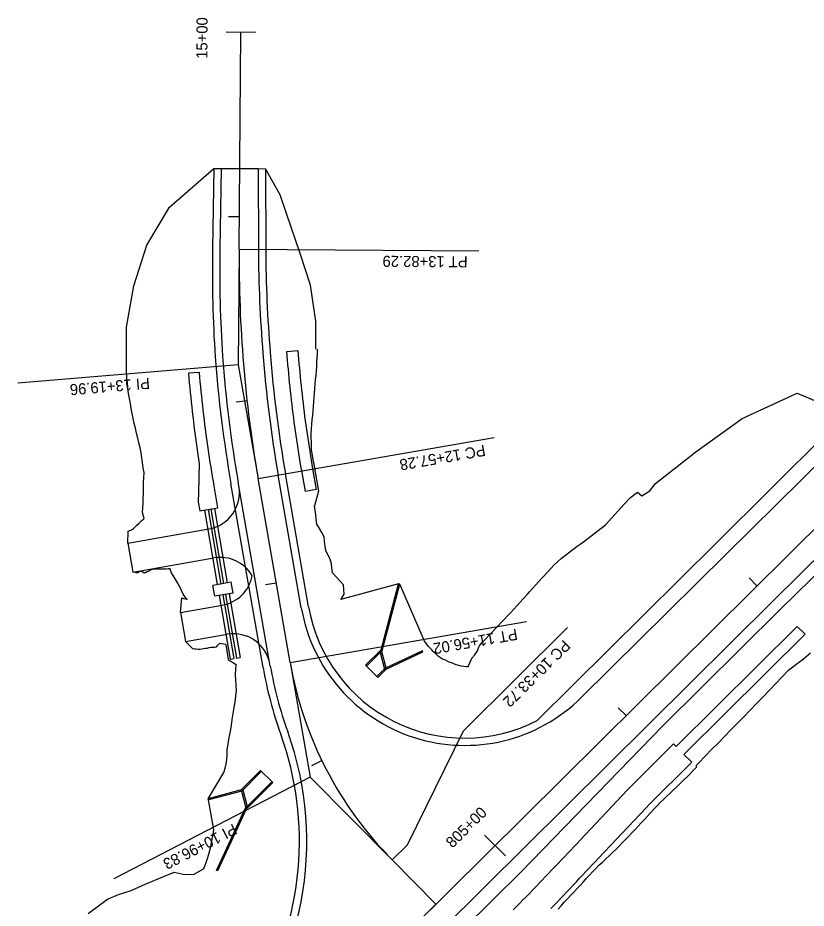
# Model space of a CAD drawing. Extents: x 1237212 to 1293764, y 379349 to 410301.
# Drawn here: x 1283553.8 to 1283981.4, y 404564.5 to 405047.3 of the extents above; entities that cross this region are included whole.
import ezdxf

# ---------------------------------------------------------------- set-up
doc = ezdxf.new("R2010")
doc.units = 0
for name, color, linetype in [('B-Sub-Footing', 7, 'Continuous'), ('B-Sub-Pier Cap', 7, 'Continuous'), ('B-Tbl-Title Block', 7, 'Continuous'), ('B-Title Block (No Plot)', 7, 'Continuous'), ('R_Axis', 7, 'Continuous'), ('R_Axis Annot', 7, 'Continuous'), ('R_Exist Surface', 7, 'Continuous'), ('R_Grid Annot', 7, 'Continuous'), ('R_Shld', 7, 'Continuous')]:
    doc.layers.add(name, color=color, linetype=linetype)

msp = doc.modelspace()

# ---------------------------------------------------------------- linework, layer by layer
for points in [[(1283666.7, 405039.61), (1283682.69, 405039.49)], [(1283666.7, 405039.61), (1283682.69, 405039.49)], [(1283667.97, 404939.6), (1283673.97, 404939.55)], [(1283672.14, 404839.05), (1283678.11, 404839.71)], [(1283688.08, 404739.97), (1283693.99, 404741)], [(1283713.3, 404641.92), (1283718.69, 404644.53)], [(1283774.89, 404561.11), (1283786.25, 404572.37)]]:
    msp.add_lwpolyline(points)
at = {"layer": 'B-Sub-Footing'}
for p, q in [((1283613.47, 404762.48), (1283657.44, 404770.15)), ((1283613.47, 404762.48), (1283616.22, 404746.72)), ((1283616.22, 404746.72), (1283660.19, 404754.39)), ((1283641.96, 404724.82), (1283664.66, 404728.78)), ((1283641.96, 404724.82), (1283644.71, 404709.06)), ((1283644.71, 404709.06), (1283667.41, 404713.02))]:
    msp.add_line(p, q, dxfattribs=at)
for centre, start, end in [((1283654, 404789.86), 279.8958, 9.8958), ((1283663.63, 404734.69), 30.3831, 99.8958), ((1283661.22, 404748.48), 279.8958, 349.4085), ((1283670.85, 404693.31), 9.8958, 99.8958)]:
    msp.add_arc(centre, 20, start, end, dxfattribs=at)
at = {"layer": 'B-Sub-Pier Cap'}
for p, q in [((1283699.71, 404866.4), (1283705.7, 404866.86)), ((1283652.29, 404855.06), (1283646.31, 404854.53)), ((1283715.65, 404791.45), (1283709.74, 404790.42)), ((1283652.5, 404779.91), (1283662.36, 404781.61)), ((1283669.47, 404741.23), (1283659.61, 404739.53)), ((1283660.65, 404733.62), (1283659.61, 404739.53)), ((1283670.51, 404735.32), (1283669.47, 404741.23)), ((1283670.51, 404735.32), (1283660.65, 404733.62)), ((1283976.49, 404717.27), (1283910.8, 404652.15)), ((1283980.72, 404713.01), (1283976.49, 404717.27)), ((1283915.03, 404647.89), (1283980.72, 404713.01)), ((1283910.8, 404652.15), (1283909.39, 404653.57)), ((1283919.25, 404643.63), (1283915.03, 404647.89))]:
    msp.add_line(p, q, dxfattribs=at)
for points in [[(1283709.74, 404790.42), (1283707.76, 404801.77), (1283707.35, 404804.14), (1283706.95, 404806.52), (1283706.55, 404808.9), (1283706.17, 404811.29), (1283705.79, 404813.67), (1283705.43, 404816.06), (1283705.07, 404818.44), (1283704.72, 404820.83), (1283704.38, 404823.22), (1283704.05, 404825.61), (1283703.72, 404828), (1283703.41, 404830.4), (1283703.1, 404832.79), (1283702.8, 404835.18), (1283702.51, 404837.58), (1283702.23, 404839.98), (1283701.96, 404842.38), (1283701.7, 404844.78), (1283701.44, 404847.18), (1283701.19, 404849.58), (1283700.96, 404851.98), (1283700.73, 404854.38), (1283700.51, 404856.78), (1283700.3, 404859.19), (1283700.09, 404861.59), (1283699.9, 404864), (1283699.71, 404866.4)], [(1283705.7, 404866.86), (1283705.88, 404864.47), (1283706.07, 404862.09), (1283706.27, 404859.7), (1283706.48, 404857.32), (1283706.7, 404854.94), (1283706.93, 404852.56), (1283707.16, 404850.18), (1283707.41, 404847.8), (1283707.66, 404845.42), (1283707.92, 404843.04), (1283708.19, 404840.67), (1283708.47, 404838.29), (1283708.76, 404835.91), (1283709.05, 404833.54), (1283709.36, 404831.17), (1283709.67, 404828.8), (1283709.99, 404826.43), (1283710.32, 404824.06), (1283710.66, 404821.69), (1283711, 404819.32), (1283711.36, 404816.96), (1283711.72, 404814.59), (1283712.09, 404812.23), (1283712.47, 404809.87), (1283712.86, 404807.51), (1283713.26, 404805.15), (1283713.67, 404802.79), (1283715.65, 404791.45)], [(1283646.31, 404854.53), (1283646.54, 404851.94), (1283646.78, 404849.34), (1283647.02, 404846.74), (1283647.28, 404844.15), (1283647.55, 404841.55), (1283647.82, 404838.96), (1283648.11, 404836.36), (1283648.4, 404833.77), (1283648.71, 404831.18), (1283649.02, 404828.59), (1283649.34, 404826), (1283649.67, 404823.41), (1283650.01, 404820.83), (1283650.36, 404818.24), (1283650.72, 404815.66), (1283651.09, 404813.08), (1283651.47, 404810.5), (1283651.86, 404807.92), (1283652.21, 404805.62), (1283652.13, 404803.25), (1283652.05, 404800.59), (1283651.98, 404797.93), (1283651.92, 404795.27), (1283651.87, 404792.62), (1283651.81, 404790.07), (1283651.67, 404784.68), (1283652.5, 404779.91)], [(1283662.36, 404781.61), (1283660.29, 404793.49), (1283659.85, 404796.05), (1283659.42, 404798.6), (1283659, 404801.15), (1283658.58, 404803.7), (1283658.18, 404806.26), (1283657.79, 404808.82), (1283657.4, 404811.38), (1283657.03, 404813.94), (1283656.66, 404816.5), (1283656.31, 404819.06), (1283655.96, 404821.62), (1283655.62, 404824.19), (1283655.29, 404826.75), (1283654.97, 404829.32), (1283654.66, 404831.89), (1283654.36, 404834.46), (1283654.07, 404837.03), (1283653.79, 404839.6), (1283653.52, 404842.17), (1283653.25, 404844.75), (1283653, 404847.32), (1283652.75, 404849.9), (1283652.52, 404852.47), (1283652.29, 404855.06)], [(1283909.39, 404653.57), (1283886.18, 404630.56), (1283884.48, 404628.61), (1283858.78, 404601.42), (1283857.06, 404599.6), (1283855.34, 404597.78), (1283853.63, 404595.96), (1283851.91, 404594.14), (1283850.19, 404592.31), (1283849.69, 404591.78), (1283848.49, 404590.52), (1283846.76, 404588.71), (1283845.04, 404586.89), (1283843.31, 404585.08), (1283841.59, 404583.27), (1283839.87, 404581.45), (1283838.14, 404579.64), (1283836.42, 404577.82), (1283834.74, 404576.05), (1283833.01, 404574.31), (1283831.25, 404572.53), (1283829.5, 404570.75), (1283827.74, 404568.97), (1283825.98, 404567.19), (1283824.22, 404565.41), (1283822.47, 404563.63)], [(1283842.91, 404564.4), (1283844.68, 404566.19), (1283846.41, 404568.01), (1283848.13, 404569.82), (1283849.85, 404571.64), (1283851.57, 404573.45), (1283853.29, 404575.26), (1283855.02, 404577.08), (1283856.74, 404578.89), (1283858.47, 404580.7), (1283859.68, 404581.98), (1283860.19, 404582.52), (1283861.91, 404584.34), (1283863.62, 404586.16), (1283865.34, 404587.98), (1283867.06, 404589.8), (1283868.77, 404591.61), (1283894.56, 404618.9), (1283896.19, 404620.77), (1283919.25, 404643.63)]]:
    msp.add_lwpolyline(points, dxfattribs=at)
at = {"layer": 'B-Tbl-Title Block'}
for p, q in [((1283664.16, 404965.64), (1283663.4, 404921.92)), ((1283664.16, 404965.64), (1283684.16, 404965.5)), ((1283684.16, 404965.5), (1283684.27, 404921.77)), ((1283937.75, 404756.35), (1284008.92, 404826.6)), ((1283707.55, 404727.3), (1283694.99, 404799.32)), ((1283963.1, 404730.79), (1284034.21, 404801.09)), ((1283690.72, 404695.78), (1283673.31, 404795.54)), ((1283859.57, 404678.85), (1283937.75, 404756.35)), ((1283732.12, 404501.81), (1283963.1, 404730.79))]:
    msp.add_line(p, q, dxfattribs=at)
for centre, radius, start, end in [((1284368.45, 404909.96), 705.15, 179.02775, 183.75514), ((1284368.04, 404923.6), 683.77, 180.15305, 184.88011), ((1284368.31, 404916.78), 683.49, 184.30872, 189.89583), ((1284368.31, 404916.78), 705.49, 184.30872, 189.89583), ((1283796.21, 404742.77), 90, 189.8958, 314.75), ((1283899.6, 404732.22), 212.04, 189.8958, 199.8404), ((1283535.54, 404600.86), 175, 318.458, 19.8404)]:
    msp.add_arc(centre, radius, start, end, dxfattribs=at)
at = {"layer": 'B-Title Block (No Plot)'}
for p, q in [((1283673.84, 404921.85), (1283674.7, 405039.55)), ((1283673.84, 404921.85), (1283674.7, 405039.55)), ((1283673.84, 404921.85), (1283674.7, 405039.55)), ((1283673.84, 404921.85), (1283674.7, 405039.55)), ((1283723.67, 404510.34), (1284167.7, 404950.51)), ((1283723.67, 404510.34), (1284167.7, 404950.51)), ((1283725.52, 404512.17), (1284086.2, 404869.72)), ((1283701.55, 404697.67), (1283684.15, 404797.43)), ((1283701.55, 404697.67), (1283684.15, 404797.43)), ((1283701.55, 404697.67), (1283684.15, 404797.43)), ((1283780.57, 404566.74), (1283756.83, 404590.69)), ((1283780.57, 404566.74), (1283756.83, 404590.69)), ((1283780.57, 404566.74), (1283756.83, 404590.69))]:
    msp.add_line(p, q, dxfattribs=at)
for centre, radius, start, end in [((1284368.31, 404916.78), 694.49, 179.58194, 189.89583), ((1284368.31, 404916.78), 694.49, 179.58194, 189.89583), ((1284368.31, 404916.78), 694.49, 179.58194, 189.89583), ((1284368.31, 404916.78), 694.49, 179.58194, 189.89583), ((1283899.6, 404732.22), 201.04, 189.8958, 224.75), ((1283899.6, 404732.22), 201.04, 189.8958, 224.75), ((1283899.6, 404732.22), 201.04, 189.8958, 224.75), ((1283899.6, 404732.22), 201.04, 189.8958, 224.75)]:
    msp.add_arc(centre, radius, start, end, dxfattribs=at)
at = {"layer": 'R_Axis'}
msp.add_line((1283765.12, 404598.91), (1283795.45, 404660.71), dxfattribs=at)
for points in [[(1283673.84, 404921.85), (1283673.38, 404859.17), (1283684.15, 404797.43)], [(1283673.84, 404921.85), (1283803.83, 404920.9)], [(1283673.38, 404859.17), (1283553.79, 404849.26)], [(1283684.15, 404797.43), (1283812.22, 404819.77)], [(1283701.55, 404697.67), (1283829.62, 404720.01)], [(1283795.45, 404660.71), (1283851.99, 404716.75)], [(1283701.55, 404697.67), (1283712.4, 404635.51), (1283756.83, 404590.69)], [(1283712.4, 404635.51), (1283605.79, 404580.43)], [(1283756.83, 404590.69), (1283765.12, 404598.91)]]:
    msp.add_lwpolyline(points, dxfattribs=at)
at = {"layer": 'R_Axis Annot'}
for p, q in [((1283655.02, 404780.35), (1283656.99, 404780.69)), ((1283655.02, 404780.35), (1283661.98, 404739.94)), ((1283656.99, 404780.69), (1283663.95, 404740.28)), ((1283658.47, 404780.94), (1283660.44, 404781.28)), ((1283658.47, 404780.94), (1283665.43, 404740.54)), ((1283660.44, 404781.28), (1283667.4, 404740.88)), ((1283663.95, 404740.28), (1283661.98, 404739.94)), ((1283667.4, 404740.88), (1283665.43, 404740.54)), ((1283750.77, 404704.6), (1283760.32, 404740.34)), ((1283751.36, 404704.25), (1283760.97, 404740.17)), ((1283760.32, 404740.34), (1283760.97, 404740.17)), ((1283668.42, 404734.96), (1283666.45, 404734.62)), ((1283666.45, 404734.62), (1283672.4, 404700.13)), ((1283668.42, 404734.96), (1283674.37, 404700.47)), ((1283664.97, 404734.37), (1283663, 404734.03)), ((1283663, 404734.03), (1283668.95, 404699.54)), ((1283664.97, 404734.37), (1283670.92, 404699.88)), ((1283742.42, 404696.24), (1283750.77, 404704.6)), ((1283742.89, 404695.77), (1283751.36, 404704.25)), ((1283750.06, 404703.89), (1283752.85, 404693.48)), ((1283750.77, 404704.6), (1283753.56, 404694.19)), ((1283773.21, 404704.1), (1283753.17, 404694.74)), ((1283753.56, 404694.19), (1283773.5, 404703.5)), ((1283773.5, 404703.5), (1283773.21, 404704.1)), ((1283668.95, 404699.54), (1283670.92, 404699.88)), ((1283672.4, 404700.13), (1283674.37, 404700.47)), ((1283742.42, 404696.24), (1283749.02, 404689.64)), ((1283748.55, 404690.12), (1283753.22, 404694.78)), ((1283749.02, 404689.64), (1283753.56, 404694.19)), ((1283674.89, 404628.64), (1283685.48, 404639.24)), ((1283675.24, 404628.04), (1283685.95, 404638.76)), ((1283685.48, 404639.24), (1283692.08, 404632.64)), ((1283674.89, 404628.64), (1283657.03, 404623.84)), ((1283674.89, 404628.64), (1283677.69, 404618.23)), ((1283675.6, 404629.35), (1283678.4, 404618.94)), ((1283677.09, 404618.58), (1283691.61, 404633.11)), ((1283677.69, 404618.23), (1283692.08, 404632.64)), ((1283657.03, 404623.84), (1283657.2, 404623.2)), ((1283675.24, 404628.04), (1283657.2, 404623.2)), ((1283661.47, 404584.97), (1283677.13, 404618.62)), ((1283677.69, 404618.23), (1283662.07, 404584.69)), ((1283662.07, 404584.69), (1283661.47, 404584.97))]:
    msp.add_line(p, q, dxfattribs=at)
at = {"layer": 'R_Exist Surface'}
for p, q in [((1283666.56, 404707.53), (1283667.96, 404699.37)), ((1283667.96, 404699.37), (1283672.21, 404696.6))]:
    msp.add_line(p, q, dxfattribs=at)
for points in [[(1283612.81, 404859.86), (1283612.81, 404879.61), (1283616.64, 404901.93), (1283623.83, 404924.02), (1283636.07, 404944.66), (1283660.16, 404965.67)], [(1283715.43, 404867.59), (1283715.43, 404882.73), (1283712.6, 404902.41), (1283706.84, 404919.46), (1283699.53, 404941.1), (1283696.06, 404951.39), (1283688.15, 404965.47)], [(1283713.1, 404812.26), (1283713.04, 404814.8), (1283712.98, 404817.2), (1283712.93, 404819.61), (1283712.94, 404822.02), (1283713.07, 404824.44), (1283713.28, 404826.88), (1283713.51, 404829.31), (1283713.73, 404831.74), (1283713.96, 404834.16), (1283714.19, 404836.58), (1283714.39, 404838.99), (1283714.52, 404841.39), (1283714.65, 404843.79), (1283714.87, 404846.2), (1283715.09, 404848.6), (1283715.31, 404851), (1283715.53, 404853.39), (1283715.75, 404855.79), (1283715.9, 404858.17), (1283716.04, 404860.55), (1283716.2, 404862.92), (1283716.31, 404865.3), (1283716.35, 404867.66)], [(1283622.39, 404775.74), (1283621.44, 404779.1), (1283621.56, 404781.66), (1283621.7, 404784.22), (1283621.83, 404786.8), (1283621.9, 404789.58), (1283621.91, 404792.35), (1283621.98, 404795.12), (1283622.09, 404797.89), (1283622.23, 404800.66), (1283621.81, 404803.35), (1283621.42, 404806.04), (1283621.03, 404808.73), (1283620.64, 404811.42), (1283620.14, 404814.09), (1283619.47, 404816.75), (1283618.81, 404819.4), (1283618.18, 404822.07), (1283617.56, 404824.73), (1283616.96, 404827.4), (1283616.38, 404830.08), (1283615.82, 404832.76), (1283615.28, 404835.44), (1283614.89, 404838.14), (1283614.41, 404840.83), (1283613.89, 404843.52), (1283613.38, 404846.22), (1283612.9, 404848.91), (1283612.81, 404859.86)], [(1283899.59, 404794.85), (1283921.44, 404811.94), (1283946.62, 404830.09), (1283976.38, 404843.72), (1284003.02, 404832.56)], [(1283713.1, 404812.26), (1283713.46, 404810.03), (1283713.85, 404807.67), (1283714.25, 404805.32), (1283714.65, 404802.96), (1283716.8, 404790.64), (1283714.75, 404782.69)], [(1283798.05, 404695.39), (1283798.92, 404697.54), (1283799.95, 404700.05), (1283801.65, 404701.89), (1283803.01, 404704.07), (1283803.98, 404706.65), (1283805.67, 404708.49), (1283807.36, 404710.34), (1283809.05, 404712.18), (1283810.8, 404713.97), (1283812.57, 404715.73), (1283814.29, 404717.55), (1283816.01, 404719.37), (1283817.72, 404721.19), (1283819.44, 404723.01), (1283821.16, 404724.83), (1283822.84, 404726.68), (1283824.51, 404728.54), (1283826.19, 404730.4), (1283827.88, 404732.25), (1283828.39, 404732.82), (1283830.14, 404734.74), (1283831.24, 404735.96), (1283834.61, 404739.66), (1283837.98, 404743.37), (1283841.35, 404747.07), (1283844.72, 404750.77), (1283848.43, 404754.13), (1283852.47, 404757.16), (1283856.5, 404760.19), (1283860.54, 404763.22), (1283864.58, 404766.25), (1283868.61, 404769.28), (1283872.57, 404772.4), (1283875.93, 404776.11), (1283879.29, 404779.82), (1283882.65, 404783.53), (1283886.01, 404787.24), (1283889.85, 404790.13), (1283892.16, 404788.14), (1283896.61, 404790.75), (1283899.59, 404794.85)], [(1283715.97, 404772.75), (1283715.66, 404775.23), (1283715.35, 404777.72), (1283715.02, 404780.2), (1283714.75, 404782.69)], [(1283613.47, 404762.48), (1283613.57, 404768.89), (1283614.55, 404769.27), (1283615.53, 404769.65), (1283616.49, 404770.35), (1283617.45, 404771.25), (1283618.4, 404772.16), (1283619.35, 404773.06), (1283620.31, 404773.97), (1283621.26, 404774.87), (1283622.22, 404775.69), (1283622.39, 404775.74)], [(1283798.05, 404695.39), (1283797.06, 404695.41), (1283795.66, 404695.55), (1283794.28, 404695.78), (1283792.92, 404696.1), (1283791.6, 404696.5), (1283790.3, 404696.98), (1283789.04, 404697.52), (1283787.79, 404697.99), (1283786.57, 404698.52), (1283785.39, 404699.11), (1283784.19, 404699.57), (1283783.07, 404700.23), (1283782.02, 404701.06), (1283781.02, 404701.92), (1283780.05, 404702.79), (1283779.13, 404703.68), (1283778.24, 404704.58), (1283777.38, 404705.5), (1283776.56, 404706.42), (1283775.78, 404707.36), (1283775.04, 404708.31), (1283774.33, 404709.26), (1283760.97, 404740.17), (1283760.32, 404740.34), (1283729.06, 404731.89), (1283730.87, 404734.75), (1283730.48, 404739.75), (1283728.46, 404741.94), (1283726.47, 404744.13), (1283724.51, 404746.32), (1283724.12, 404748.8), (1283723.97, 404751.31), (1283723.15, 404753.7), (1283721.97, 404756.03), (1283720.81, 404758.37), (1283720.44, 404760.84), (1283720.19, 404763.34), (1283719.86, 404765.82), (1283718.65, 404768.14), (1283717.35, 404770.45), (1283715.97, 404772.75)], [(1283616.87, 404746.83), (1283617.92, 404746.6), (1283618.96, 404746.44), (1283619.89, 404746.98), (1283620.81, 404747.52)], [(1283620.81, 404747.52), (1283621.97, 404746.56), (1283622.98, 404746.56), (1283623.93, 404747), (1283624.87, 404747.44), (1283625.82, 404747.89), (1283626.76, 404748.33), (1283627.74, 404748.52)], [(1283627.74, 404748.52), (1283628.75, 404748.51), (1283629.81, 404748.52), (1283630.91, 404748.55), (1283632.01, 404748.56), (1283633.11, 404748.59), (1283634.22, 404748.6), (1283635.33, 404748.61), (1283636.15, 404748.73)], [(1283645.67, 404731.91), (1283645.11, 404732.47), (1283643.55, 404734.74), (1283642.44, 404737.08), (1283641.33, 404739.43), (1283639.96, 404741.73), (1283638.57, 404744.02), (1283637.18, 404746.32), (1283636.15, 404748.73)], [(1283641.96, 404724.82), (1283642.66, 404732.71), (1283643.71, 404732.47), (1283644.77, 404732.23), (1283645.67, 404731.91)], [(1283644.71, 404709.06), (1283648.46, 404705.23), (1283649.49, 404705.15), (1283650.52, 404705.06), (1283651.55, 404704.97), (1283652.56, 404705.04), (1283653.55, 404705.18), (1283654.54, 404705.33), (1283655.54, 404705.43), (1283656.53, 404705.56), (1283657.48, 404705.94), (1283658.48, 404705.98), (1283659.49, 404706.01), (1283660.51, 404706.03), (1283661.47, 404706.31), (1283662.35, 404707.12), (1283663.26, 404707.97)], [(1283666.56, 404707.53), (1283663.26, 404707.97)], [(1283846.79, 404564.03), (1283848.48, 404565.87), (1283850.18, 404567.71), (1283851.87, 404569.55), (1283853.57, 404571.39), (1283855.29, 404573.21), (1283857.01, 404575.02), (1283858.72, 404576.85), (1283860.42, 404578.69), (1283861.61, 404579.98), (1283862.11, 404580.53), (1283863.79, 404582.39), (1283865.48, 404584.24), (1283867.2, 404586.05), (1283868.98, 404587.81), (1283870.81, 404589.51), (1283872.65, 404591.21), (1283874.48, 404592.91), (1283876.27, 404594.66), (1283878.06, 404596.41), (1283879.84, 404598.15), (1283881.63, 404599.9), (1283883.37, 404601.7), (1283885.09, 404603.52), (1283886.81, 404605.33), (1283888.52, 404607.15), (1283890.22, 404609), (1283891.91, 404610.84), (1283893.61, 404612.67), (1283895.33, 404614.49), (1283897.05, 404616.31), (1283898.66, 404618.24), (1283900.45, 404619.98), (1283902.23, 404621.73), (1283904.03, 404623.47), (1283905.85, 404625.19), (1283907.66, 404626.91), (1283909.47, 404628.64), (1283911.25, 404630.39), (1283913.04, 404632.14), (1283914.83, 404633.89), (1283916.61, 404635.63), (1283918.4, 404637.38), (1283920.1, 404639.22), (1283920.61, 404639.78), (1283921.79, 404641.06), (1283921.94, 404642.13), (1283923.06, 404643.33), (1283926.52, 404646.95), (1283930.06, 404650.48), (1283933.6, 404654.01), (1283937.03, 404657.66), (1283940.49, 404661.26), (1283944.03, 404664.8), (1283947.57, 404668.33), (1283951.02, 404671.95), (1283954.47, 404675.57), (1283957.95, 404679.16), (1283961.43, 404682.75), (1283964.91, 404686.34), (1283968.39, 404689.94), (1283971.84, 404693.56), (1283975.81, 404696.66), (1283979.71, 404699.48), (1283979.91, 404699.63), (1283983.63, 404702.98)], [(1283654.52, 404585.88), (1283654.86, 404586.4), (1283655.96, 404589.22), (1283656.84, 404591.95), (1283657.61, 404594.61), (1283658.31, 404597.19), (1283658.81, 404599.71), (1283659.28, 404602.17), (1283659.71, 404604.57), (1283660.12, 404606.93), (1283657.2, 404623.2), (1283657.03, 404623.84), (1283665.56, 404638.11), (1283666.17, 404640.44), (1283666.77, 404642.8), (1283667.15, 404645.13), (1283667.36, 404647.42), (1283667.42, 404650.24), (1283667.87, 404653.62), (1283668.47, 404657.02), (1283669.09, 404660.38), (1283669.6, 404663.67), (1283670.04, 404666.89), (1283670.55, 404670.11), (1283671.07, 404673.29), (1283671.61, 404676.44), (1283671.96, 404679.52), (1283672.31, 404682.57), (1283672.3, 404685.52), (1283672.06, 404688.41), (1283671.84, 404691.3), (1283672.02, 404694.03), (1283672.21, 404696.6)], [(1283591.89, 404561.64), (1283602.47, 404569.32), (1283608.38, 404571.9), (1283615.26, 404574.09), (1283622.88, 404577.6), (1283638.57, 404584.03), (1283643.53, 404582.97), (1283649.03, 404582.72), (1283654.52, 404585.88)]]:
    msp.add_lwpolyline(points, dxfattribs=at)
at = {"layer": 'R_Grid Annot'}
for points in [[(1283950.42, 404743.57), (1283954.65, 404739.31)], [(1283950.42, 404743.57), (1283954.65, 404739.31)], [(1283879.41, 404673.17), (1283883.63, 404668.91)], [(1283879.41, 404673.17), (1283883.63, 404668.91)], [(1283806.98, 404604.19), (1283818.24, 404592.83)], [(1283806.98, 404604.19), (1283818.24, 404592.83)]]:
    msp.add_lwpolyline(points, dxfattribs=at)
at = {"layer": 'R_Shld'}
for p, q in [((1283660.16, 404965.67), (1283659.4, 404921.95)), ((1283660.16, 404965.67), (1283664.16, 404965.64)), ((1283684.16, 404965.5), (1283688.15, 404965.47)), ((1283688.15, 404965.47), (1283688.27, 404921.74)), ((1283932.12, 404762.04), (1284003.02, 404832.56)), ((1283711.49, 404727.99), (1283698.93, 404800)), ((1283686.78, 404695.1), (1283669.37, 404794.85)), ((1283967.32, 404726.53), (1284038.56, 404796.7)), ((1283835.53, 404666.29), (1283932.12, 404762.04)), ((1283903.4, 404663.16), (1283967.32, 404726.53)), ((1283903.4, 404663.16), (1283826.69, 404584.3)), ((1283737.75, 404496.13), (1283826.69, 404584.3))]:
    msp.add_line(p, q, dxfattribs=at)
for centre, radius, start, end in [((1284368.45, 404909.96), 709.15, 179.02775, 183.75514), ((1284368.04, 404923.6), 679.77, 180.15305, 184.88011), ((1284368.31, 404916.78), 679.49, 184.30872, 189.89583), ((1284368.31, 404916.78), 709.49, 184.30872, 189.89583), ((1283796.21, 404742.77), 86, 189.8958, 297.2065), ((1283899.6, 404732.22), 216.04, 189.8958, 199.8404), ((1283535.54, 404600.86), 171, 329.8592, 19.8404)]:
    msp.add_arc(centre, radius, start, end, dxfattribs=at)

# ---------------------------------------------------------------- texts
msp.add_text('15+00', height=6, rotation=89.5819).set_placement((1283656.59, 405025.04))
msp.add_text('15+00', height=6, rotation=89.5819).set_placement((1283656.59, 405025.04))
at = {"layer": 'R_Axis'}
for s, rotation, p in [('PT 13+82.29', 179.5819, (1283797.81, 404917.94)), ('PI 13+19.96', 184.7389, (1283625.17, 404852.16)), ('PC 12+57.28', 189.8958, (1283806.82, 404815.78)), ('PT 11+56.02', 189.8958, (1283824.22, 404716.03)), ('PC 10+33.72', 224.75, (1283849.84, 404710.4)), ('PI 10+96.83', 207.3229, (1283670.57, 404610.52))]:
    msp.add_text(s, height=6, rotation=rotation, dxfattribs=at).set_placement(p)
at = {"layer": 'R_Grid Annot'}
msp.add_text('805+00', height=6, rotation=44.75, dxfattribs=at).set_placement((1283789.52, 404596.74))

doc.saveas('drawing.dxf')
